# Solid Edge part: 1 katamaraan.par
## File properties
Author: Henri
Template: Normal.par
Last saved by: Henri
Revision: 92
Application: Solid Edge
Accuracy: 0,990
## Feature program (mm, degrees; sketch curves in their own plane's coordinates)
make body feature "unnamed MakeBodyFeature 1"
body pattern "unnamed BodyPattern 1"
pattern "unnamed Pattern 1"
sketch used by "ExtrudedCutout_22" plane through (0, 0, 0) normal (0, -1, 0) x-axis (1, 0, 0)
  arc centre (-269.3654, -198.9808) radius 198.9808 from (-425, -75) to (-269.3654, 0) cw
  line (-425, -75) -> (-425, 0)
  line (-425, 0) -> (-269.3654, 0)
extrude "ExtrudedCutout_22" cut finite 150 symmetric
fillet "Round_5" radius 10
thinwall "Thinwall_9"  Thickness = 5 mm
sketch for "unnamed Protrusion 1" plane through (0, 0, 0) normal (0, -1, 0) x-axis (1, 0, 0)
  line (-358, -40.9709) -> (-327, -40.9709)
  line (-327, -40.9709) -> (-327, -26.9709)
  line (-327, -26.9709) -> (-296, -26.9709)
  line (-296, -26.9709) -> (-296, -12.9709)
  line (-296, -12.9709) -> (-265, -12.9709)
  line (-265, -12.9709) -> (-265, 0)
  line (-265, 0) -> (-260, 0)
  line (-260, -142.3581) -> (-260, 0)
  line (-265, -142.3562) -> (-260, -142.3581)
  line (-265, -17.9709) -> (-265, -142.3562)
  line (-291, -17.9709) -> (-265, -17.9709)
  line (-291, -31.9709) -> (-291, -17.9709)
  line (-322, -31.9709) -> (-291, -31.9709)
  line (-322, -45.9709) -> (-322, -31.9709)
  line (-353, -45.9709) -> (-322, -45.9709)
  line (-353, -59.9709) -> (-353, -45.9709)
  line (-384, -59.9709) -> (-353, -59.9709)
  line (-384, -73.9709) -> (-384, -59.9709)
  line (-420, -73.9709) -> (-384, -73.9709)
  line (-420, -68.9709) -> (-420, -73.9709)
  line (-420, -68.9709) -> (-389, -68.9709)
  line (-389, -68.9709) -> (-389, -54.9709)
  line (-389, -54.9709) -> (-358, -54.9709)
  line (-358, -54.9709) -> (-358, -40.9709)
extrude "unnamed Protrusion 1" add through along -normal
sketch for "ExtrudedCutout_24" plane through (-260, 0, -71.179) normal (1, 0, 0) x-axis (0, 1, 0)
  line (22.5, -30.321) -> (22.5, 53.2082)
  line (22.5, 53.2082) -> (-22.5, 53.2082)
  line (-22.5, 53.2082) -> (-22.5, -30.321)
  line (-22.5, -30.321) -> (22.5, -30.321)
extrude "ExtrudedCutout_24" cut finite 5 along -normal
web network "WebNetwork_20"  Thickness = 3 mm
web network "WebNetwork_21"  Thickness = 5 mm
sketch used by "unnamed Cutout 1" plane through (2.5, 0, -49.25) normal (1, 0, 0) x-axis (0, 1, 0)
extrude "unnamed Cutout 1" cut through along -normal
sketch used by "unnamed Cutout 2" plane through (262.5, 0, -57.5536) normal (1, 0, 0) x-axis (0, 1, 0)
  line (-15, 52.5536) -> (15, 52.5536)
  line (-15, 52.5536) -> (-15, 17.5536)
  line (-15, 17.5536) -> (15, 17.5536)
  line (15, 17.5536) -> (15, 52.5536)
extrude "unnamed Cutout 2" cut through along -normal
sketch for "ExtrudedCutout_27" plane through (0, 0, -150) normal (0, 0, 1) x-axis (1, 0, 0)
  circle centre (-356.0086, 0) radius 2.5
extrude "ExtrudedCutout_27" cut finite 5 along +normal
body pattern "unnamed BodyPattern 2"
pattern "unnamed Pattern 2"
fillet "Round_26" radius 2.5
fillet "Round_27" radius 2.5
fillet "Round_28" radius 1.5
fillet "Round_29" radius 1.5
sketch for "unnamed Protrusion 2" plane through (0, -250, 0) normal (0, -1, 0) x-axis (1, 0, 0)
  line (-222.5, 0) -> (262.5, 0)
  line (262.5, 0) -> (262.5, -49)
  arc centre (261.5, -49) radius 1 from (261.5, -50) to (262.5, -49) ccw
  line (261.5, -50) -> (248.5, -50)
  arc centre (248.5, -49) radius 1 from (247.5, -49) to (248.5, -50) ccw
  line (247.5, -46) -> (247.5, -49)
  arc centre (246.5, -46) radius 1 from (246.5, -45) to (247.5, -46) cw
  line (158.5, -45) -> (246.5, -45)
  arc centre (158.5, -46) radius 1 from (157.5, -46) to (158.5, -45) cw
  line (157.5, -51.1299) -> (157.5, -46)
  arc centre (156.5, -51.1299) radius 1 from (156.5, -52.1299) to (157.5, -51.1299) ccw
  line (33.5, -52.1299) -> (156.5, -52.1299)
  arc centre (33.5, -51.1299) radius 1 from (32.5, -51.1299) to (33.5, -52.1299) ccw
  line (32.5, -46) -> (32.5, -51.1299)
  arc centre (31.5, -46) radius 1 from (31.5, -45) to (32.5, -46) cw
  line (-206.5, -45) -> (31.5, -45)
  arc centre (-206.5, -46) radius 1 from (-207.5, -46) to (-206.5, -45) cw
  line (-207.5, -46) -> (-207.5, -49)
  arc centre (-208.5, -49) radius 1 from (-208.5, -50) to (-207.5, -49) ccw
  line (-221.5, -50) -> (-208.5, -50)
  arc centre (-221.5, -49) radius 1 from (-222.5, -49) to (-221.5, -50) ccw
  line (-222.5, 0) -> (-222.5, -49)
extrude "unnamed Protrusion 2" add through along -normal
fillet "Round_30" radius 1.5
sketch for "ExtrudedCutout_47" plane through (0, 0, 0) normal (0, 0, 1) x-axis (1, 0, 0)
  line (202.5, -60) -> (212.5, -60)
  line (212.5, -60) -> (212.5, -55)
  line (212.5, -55) -> (202.5, -55)
  line (202.5, -55) -> (202.5, -60)
extrude "ExtrudedCutout_47" cut finite 5 along -normal
sketch for "ExtrudedCutout_49" plane through (0, 0, 0) normal (0, 0, 1) x-axis (1, 0, 0)
  line (-207.5, -75) -> (242.5, -75)
  line (242.5, -75) -> (242.5, -425)
  line (242.5, -425) -> (-207.5, -425)
  line (-207.5, -75) -> (-207.5, -425)
  line (-210, -72.5) -> (-210, -427.5)
  line (-210, -427.5) -> (245, -427.5)
  line (245, -427.5) -> (245, -72.5)
  line (245, -72.5) -> (-210, -72.5)
  dimension (linear) = 242.5
extrude "ExtrudedCutout_49" cut finite 37.5 along -normal
sketch for "unnamed Cutout 3" plane through (17.5, -72.5, -18.75) normal (0, -1, 0) x-axis (1, 0, 0)
  line (140, 18.75) -> (140, -18.75)
  line (80, -18.75) -> (140, -18.75)
  line (80, 18.75) -> (80, -18.75)
  line (140, 18.75) -> (80, 18.75)
extrude "unnamed Cutout 3" cut through along -normal
sketch for "unnamed Cutout 4" plane through (17.5, -427.5, -18.75) normal (0, 1, 0) x-axis (1, 0, 0)
extrude "unnamed Cutout 4" cut through along -normal
swept protrusion "unnamed SweptProtrusion 1"
swept protrusion "unnamed SweptProtrusion 2"
sketch for "unnamed Protrusion 3" #1 plane through (0, 0, 0) normal (0, -1, 0) x-axis (1, 0, 0)
  line (0, 0) -> (0, 0)
  line (98.5, -48.5) -> (156.5, -48.5)
  arc centre (156.5, -49.5) radius 1 from (156.5, -48.5) to (157.5, -49.5) cw
  line (157.5, -49.5) -> (157.5, -50)
  arc centre (156.5, -50) radius 1 from (156.5, -51) to (157.5, -50) ccw
  line (98.5, -51) -> (156.5, -51)
  arc centre (98.5, -50) radius 1 from (97.5, -50) to (98.5, -51) ccw
  line (97.5, -49.5) -> (97.5, -50)
  arc centre (98.5, -49.5) radius 1 from (97.5, -49.5) to (98.5, -48.5) cw
sketch for "unnamed Protrusion 3" #2 plane through (0, 0, 0) normal (0, -1, 0) x-axis (1, 0, 0)
  line (98.5, -61) -> (156.5, -61)
  arc centre (156.5, -62) radius 1 from (156.5, -61) to (157.5, -62) cw
  line (157.5, -62) -> (157.5, -62.5)
  arc centre (156.5, -62.5) radius 1 from (157.5, -62.5) to (156.5, -63.5) cw
  line (98.5, -63.5) -> (156.5, -63.5)
  arc centre (98.5, -62.5) radius 1 from (98.5, -63.5) to (97.5, -62.5) cw
  line (97.5, -62) -> (97.5, -62.5)
  arc centre (98.5, -62) radius 1 from (97.5, -62) to (98.5, -61) cw
sketch for "unnamed Protrusion 3" #3 plane through (0, 0, 0) normal (0, -1, 0) x-axis (1, 0, 0)
  line (98.5, -73.5) -> (156.5, -73.5)
  arc centre (156.5, -74.5) radius 1 from (156.5, -73.5) to (157.5, -74.5) cw
  line (157.5, -74.5) -> (157.5, -75)
  arc centre (156.5, -75) radius 1 from (157.5, -75) to (156.5, -76) cw
  line (98.5, -76) -> (156.5, -76)
  arc centre (98.5, -75) radius 1 from (97.5, -75) to (98.5, -76) ccw
  line (97.5, -74.5) -> (97.5, -75)
  arc centre (98.5, -74.5) radius 1 from (97.5, -74.5) to (98.5, -73.5) cw
sketch for "unnamed Protrusion 3" #4 plane through (0, 0, 0) normal (0, -1, 0) x-axis (1, 0, 0)
  line (98.5, -86) -> (156.5, -86)
  arc centre (156.5, -87) radius 1 from (156.5, -86) to (157.5, -87) cw
  line (157.5, -87) -> (157.5, -87.5)
  arc centre (156.5, -87.5) radius 1 from (157.5, -87.5) to (156.5, -88.5) cw
  line (98.5, -88.5) -> (156.5, -88.5)
  arc centre (98.5, -87.5) radius 1 from (97.5, -87.5) to (98.5, -88.5) ccw
  line (97.5, -87) -> (97.5, -87.5)
  arc centre (98.5, -87) radius 1 from (98.5, -86) to (97.5, -87) ccw
extrude "unnamed Protrusion 3" add through along +normal
sketch for "unnamed Cutout 5" plane through (152.5, 0, 0) normal (1, 0, 0) x-axis (0, 1, 0)
  line (0, -47.323) -> (-13.7556, -47.323)
  line (0, -89.2775) -> (-13.7556, -47.323)
  line (0, -47.323) -> (0, -89.2775)
extrude "unnamed Cutout 5" cut through along -normal
fillet "Round_32" radius 1
mirror "unnamed Mirror 1" of "unnamed SweptProtrusion 2", "unnamed SweptProtrusion 1" about plane through (0, -250, 0) normal (0, -1, 0)
swept protrusion "unnamed SweptProtrusion 3"
swept protrusion "unnamed SweptProtrusion 4"
mirror "unnamed Mirror 2" of "unnamed Protrusion 3", "unnamed Cutout 5" about plane through (0, -250, 0) normal (0, -1, 0)
extrude "unnamed Protrusion 4" add through
extrude "unnamed Cutout 6" cut through
sketch for "ExtrudedCutout_54" plane through (-81.4374, 2.895, -98.5) normal (0, 0, 1) x-axis (0, 1, 0)
  line (22.105, 191.0626) -> (-27.895, 191.0626)
  line (-27.895, 261.0626) -> (-27.895, 191.0626)
  line (22.105, 261.0626) -> (-27.895, 261.0626)
  line (22.105, 191.0626) -> (22.105, 261.0626)
extrude "ExtrudedCutout_54" cut finite 1 along -normal
mirror "unnamed Mirror 3" of "ExtrudedCutout_54" about plane through (0, -250, 0) normal (0, -1, 0)
extrude "unnamed Cutout 7" cut finite 1
sketch used by "ExtrudedProtrusion_60" plane through (73.8141, -228.1374, 0) normal (0, 0, 1) x-axis (0, 1, 0)
extrude "ExtrudedProtrusion_60" add finite 5 along +normal  FiniteDepth2 = 50 mm
sketch for "ExtrudedCutout_60" plane through (73.8141, -228.1374, 0) normal (0, 0, 1) x-axis (0, 1, 0)
  arc centre (-17.3626, -38.6859) radius 3 from (-17.3626, -41.6859) to (-14.3626, -38.6859) ccw
  line (-14.3626, -19.6859) -> (-14.3626, -38.6859)
  arc centre (-17.3626, -19.6859) radius 3 from (-17.3626, -16.6859) to (-14.3626, -19.6859) cw
  line (-26.3626, -16.6859) -> (-17.3626, -16.6859)
  arc centre (-26.3626, -19.6859) radius 3 from (-29.3626, -19.6859) to (-26.3626, -16.6859) cw
  line (-29.3626, -19.6859) -> (-29.3626, -38.6859)
  arc centre (-26.3626, -38.6859) radius 3 from (-26.3626, -41.6859) to (-29.3626, -38.6859) cw
  line (-26.3626, -41.6859) -> (-17.3626, -41.6859)
extrude "ExtrudedCutout_60" cut finite 5 along +normal  FiniteDepth2 = 45 mm
sketch for "unnamed Protrusion 5" #1 plane through (0, -25, 0) normal (0, -1, 0) x-axis (1, 0, 0)
sketch for "unnamed Protrusion 5" #2 plane through (0, -25, 0) normal (0, -1, 0) x-axis (1, 0, 0)
sketch for "unnamed Protrusion 5" #3 plane through (0, -25, 0) normal (0, -1, 0) x-axis (1, 0, 0)
  line (14.5, -11) -> (36, -11)
  arc centre (36, -12) radius 1 from (36, -11) to (37, -12) cw
  line (37, -12) -> (37, -20)
  arc centre (36, -20) radius 1 from (36, -21) to (37, -20) ccw
  line (14.5, -21) -> (36, -21)
  arc centre (14.5, -20) radius 1 from (13.5, -20) to (14.5, -21) ccw
  line (13.5, -20) -> (13.5, -12)
  arc centre (14.5, -12) radius 1 from (13.5, -12) to (14.5, -11) cw
sketch for "unnamed Protrusion 5" #4 plane through (0, -25, 0) normal (0, -1, 0) x-axis (1, 0, 0)
  arc centre (39, -12) radius 1 from (38, -12) to (39, -11) cw
  line (39, -11) -> (60.5, -11)
  arc centre (60.5, -12) radius 1 from (60.5, -11) to (61.5, -12) cw
  line (61.5, -12) -> (61.5, -20)
  arc centre (60.5, -20) radius 1 from (60.5, -21) to (61.5, -20) ccw
  line (39, -21) -> (60.5, -21)
  arc centre (39, -20) radius 1 from (39, -21) to (38, -20) cw
  line (38, -12) -> (38, -20)
sketch for "unnamed Protrusion 5" #5 plane through (0, -25, 0) normal (0, -1, 0) x-axis (1, 0, 0)
  line (14.5, -22) -> (36, -22)
  arc centre (36, -23) radius 1 from (36, -22) to (37, -23) cw
  line (37, -23) -> (37, -41)
  arc centre (36, -41) radius 1 from (36, -42) to (37, -41) ccw
  line (14.5, -42) -> (36, -42)
  arc centre (14.5, -41) radius 1 from (14.5, -42) to (13.5, -41) cw
  line (13.5, -41) -> (13.5, -23)
  arc centre (14.5, -23) radius 1 from (13.5, -23) to (14.5, -22) cw
sketch for "unnamed Protrusion 5" #6 plane through (0, -25, 0) normal (0, -1, 0) x-axis (1, 0, 0)
  line (39, -22) -> (60.5, -22)
  arc centre (60.5, -23) radius 1 from (60.5, -22) to (61.5, -23) cw
  line (61.5, -23) -> (61.5, -41)
  arc centre (60.5, -41) radius 1 from (60.5, -42) to (61.5, -41) ccw
  line (39, -42) -> (60.5, -42)
  arc centre (39, -41) radius 1 from (38, -41) to (39, -42) ccw
  line (38, -23) -> (38, -41)
  arc centre (39, -23) radius 1 from (38, -23) to (39, -22) cw
sketch for "unnamed Protrusion 5" #7 plane through (0, -25, 0) normal (0, -1, 0) x-axis (1, 0, 0)
  line (14.5, -43) -> (36, -43)
  arc centre (36, -44) radius 1 from (36, -43) to (37, -44) cw
  line (37, -44) -> (37, -57)
  arc centre (36, -57) radius 1 from (36, -58) to (37, -57) ccw
  line (14.5, -58) -> (36, -58)
  arc centre (14.5, -57) radius 1 from (14.5, -58) to (13.5, -57) cw
  line (13.5, -57) -> (13.5, -44)
  arc centre (14.5, -44) radius 1 from (13.5, -44) to (14.5, -43) cw
sketch for "unnamed Protrusion 5" #8 plane through (0, -25, 0) normal (0, -1, 0) x-axis (1, 0, 0)
  arc centre (39, -60) radius 1 from (38, -60) to (39, -59) cw
  line (39, -59) -> (60.5, -59)
  arc centre (60.5, -60) radius 1 from (61.5, -60) to (60.5, -59) ccw
  line (61.5, -60) -> (61.5, -68)
  arc centre (60.5, -68) radius 1 from (60.5, -69) to (61.5, -68) ccw
  line (60.5, -69) -> (39, -69)
  arc centre (39, -68) radius 1 from (38, -68) to (39, -69) ccw
  line (38, -60) -> (38, -68)
sketch for "unnamed Protrusion 5" #9 plane through (0, -25, 0) normal (0, -1, 0) x-axis (1, 0, 0)
extrude "unnamed Protrusion 5" add through along +normal
fillet "Round_34" radius 1
mirror "unnamed Mirror 4" of "unnamed Protrusion 5" about plane through (0, -250, 0) normal (0, -1, 0)
extrude "unnamed Protrusion 6" add through
sketch used by "unnamed Protrusion 7" plane through (0, -5, 0) normal (0, -1, 0) x-axis (1, 0, 0)
extrude "unnamed Protrusion 7" add through along -normal
swept protrusion "unnamed SweptProtrusion 5"
sketch for "ExtrudedProtrusion_65" plane through (-81.4299, 0, -98.5) normal (0, 0, 1) x-axis (0, 1, 0)
  circle centre (20, 48.5701) radius 1.25
extrude "ExtrudedProtrusion_65" add finite 62.5 along +normal
sketch for "unnamed Protrusion 8" #1 plane through (-180, 10, -81) normal (0, -1, 0) x-axis (1, 0, 0)
  circle centre (50.053, 37.5) radius 0.75
sketch for "unnamed Protrusion 8" #2 plane through (-180, 10, -81) normal (0, -1, 0) x-axis (1, 0, 0)
  circle centre (50, 22.5) radius 0.75
sketch for "unnamed Protrusion 8" #3 plane through (-180, 10, -81) normal (0, -1, 0) x-axis (1, 0, 0)
  circle centre (50, 7.5) radius 0.75
sketch for "unnamed Protrusion 8" #4 plane through (-180, 10, -81) normal (0, -1, 0) x-axis (1, 0, 0)
  circle centre (50, -7.5) radius 0.75
extrude "unnamed Protrusion 8" add through along -normal
fillet "Round_35" radius 1.5
mirror "unnamed Mirror 5" of "unnamed Protrusion 7" about plane through (0, -250, 0) normal (0, -1, 0)
extrude "unnamed Protrusion 9" add through
mirror "unnamed Mirror 6" of "unnamed SweptProtrusion 5", "ExtrudedProtrusion_65", "unnamed Protrusion 8" about plane through (0, -250, 0) normal (0, -1, 0)
swept protrusion "unnamed SweptProtrusion 6"
extrude "unnamed Protrusion 10" add finite 62.5
extrude "unnamed Protrusion 11" add through
fillet "Round_36" radius 1.5
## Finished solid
Body 1: solid body, 756 faces, 1844 edges, 1096 vertices, 2 internal voids.
  Faces by surface: plane 274, cylinder 228, blend 120, sphere 60, offset 40, spline 34
  Edges by curve: intersection 794, line 702, circle 342, curve on surface 6
Body 2: solid body, 4 faces, 7 edges, 5 vertices.
  Faces by surface: plane 3, spline 1
  Edges by curve: line 3, curve on surface 2, circle 1, spline 1
Bounding box of the edges (mm; curved faces can reach further): 850.000 x 646.544 x 155.000, from (-425, -573.4364, -150) to (425, 73.1078, 5).
Cylindrical faces by radius (mm): R0.75 x8, R1 x146, R1.25 x4, R1.5 x36, R2.5 x24, R3 x4, R10 x4, R198.9808 x2
Spherical faces by radius (mm): R1 x32, R1.5 x16, R2.5 x12
Planar faces by outward normal: +x 59, +y 16, +z 52, -x 64, -y 17, -z 57, oblique 12
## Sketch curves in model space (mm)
circle centre (-130, 10, -88.5) radius 0.75
circle centre (-130, 10, -73.5) radius 0.75
circle centre (-129.947, 10, -43.5) radius 0.75
circle centre (-130, 10, -58.5) radius 0.75
line (-138.1822, 10, -43.5) -> (-121.7119, 10, -43.5)
line (-139.7989, 10, -58.5) -> (-123.7328, 10, -58.5)
line (-141.5166, 10, -73.5) -> (-119.8931, 10, -73.5)
line (-141.5166, 10, -88.5) -> (-117.8722, 10, -88.5)
line (-130, 10, -20.6012) -> (-130, 10, -101.0326)
circle centre (-130, 20, -98.5) radius 1.25
line (-130, -8.4576, -98.5) -> (-130, 25.6531, -98.5)
line (-134.8834, 20, -98.5) -> (-121.6792, 20, -98.5)
circle centre (-230, 0, -33.5) radius 1.25
arc centre (61.5, -25, -11) radius 1 from (61.5, -25, -10) through (62.2274, -25, -10.3138) to (62.5, -25, -11)
line (62.5, -25, -11) -> (62.5, -25, -69)
arc centre (61.5, -25, -69) radius 1 from (61.5, -25, -70) through (62.2274, -25, -69.6862) to (62.5, -25, -69)
line (61.5, -25, -70) -> (13.5, -25, -70)
arc centre (13.5, -25, -69) radius 1 from (12.5, -25, -69) through (12.8138, -25, -69.7274) to (13.5, -25, -70)
line (12.5, -25, -69) -> (12.5, -25, -11)
arc centre (13.5, -25, -11) radius 1 from (12.5, -25, -11) through (12.8138, -25, -10.2726) to (13.5, -25, -10)
line (13.5, -25, -10) -> (61.5, -25, -10)
arc centre (14.5, -25, -23) radius 1 from (13.5, -25, -23) through (13.8138, -25, -22.2726) to (14.5, -25, -22)
line (14.5, -25, -22) -> (36, -25, -22)
arc centre (36, -25, -23) radius 1 from (36, -25, -22) through (36.7274, -25, -22.3138) to (37, -25, -23)
line (37, -25, -23) -> (37, -25, -41)
arc centre (36, -25, -41) radius 1 from (36, -25, -42) through (36.7274, -25, -41.6862) to (37, -25, -41)
line (14.5, -25, -42) -> (36, -25, -42)
arc centre (14.5, -25, -41) radius 1 from (14.5, -25, -42) through (13.7726, -25, -41.6862) to (13.5, -25, -41)
line (13.5, -25, -41) -> (13.5, -25, -23)
arc centre (36, -25, -12) radius 1 from (36, -25, -11) through (36.7274, -25, -11.3138) to (37, -25, -12)
line (37, -25, -12) -> (37, -25, -20)
arc centre (36, -25, -20) radius 1 from (36, -25, -21) through (36.7274, -25, -20.6862) to (37, -25, -20)
line (14.5, -25, -21) -> (36, -25, -21)
arc centre (14.5, -25, -20) radius 1 from (13.5, -25, -20) through (13.8138, -25, -20.7274) to (14.5, -25, -21)
line (13.5, -25, -20) -> (13.5, -25, -12)
arc centre (14.5, -25, -12) radius 1 from (13.5, -25, -12) through (13.8138, -25, -11.2726) to (14.5, -25, -11)
line (14.5, -25, -11) -> (36, -25, -11)
arc centre (60.5, -25, -41) radius 1 from (60.5, -25, -42) through (61.2274, -25, -41.6862) to (61.5, -25, -41)
line (39, -25, -42) -> (60.5, -25, -42)
arc centre (39, -25, -41) radius 1 from (38, -25, -41) through (38.3138, -25, -41.7274) to (39, -25, -42)
line (38, -25, -23) -> (38, -25, -41)
arc centre (39, -25, -23) radius 1 from (38, -25, -23) through (38.3138, -25, -22.2726) to (39, -25, -22)
line (39, -25, -22) -> (60.5, -25, -22)
arc centre (60.5, -25, -23) radius 1 from (60.5, -25, -22) through (61.2274, -25, -22.3138) to (61.5, -25, -23)
line (61.5, -25, -23) -> (61.5, -25, -41)
arc centre (14.5, -25, -68) radius 1 from (13.5, -25, -68) through (13.8138, -25, -68.7274) to (14.5, -25, -69)
line (13.5, -25, -68) -> (13.5, -25, -60)
arc centre (14.5, -25, -60) radius 1 from (13.5, -25, -60) through (13.8138, -25, -59.2726) to (14.5, -25, -59)
line (14.5, -25, -59) -> (36, -25, -59)
arc centre (36, -25, -60) radius 1 from (36, -25, -59) through (36.7274, -25, -59.3138) to (37, -25, -60)
line (37, -25, -60) -> (37, -25, -68)
arc centre (36, -25, -68) radius 1 from (36, -25, -69) through (36.7274, -25, -68.6862) to (37, -25, -68)
line (36, -25, -69) -> (14.5, -25, -69)
arc centre (60.5, -25, -20) radius 1 from (60.5, -25, -21) through (61.2274, -25, -20.6862) to (61.5, -25, -20)
line (61.5, -25, -12) -> (61.5, -25, -20)
arc centre (60.5, -25, -12) radius 1 from (60.5, -25, -11) through (61.2274, -25, -11.3138) to (61.5, -25, -12)
line (39, -25, -11) -> (60.5, -25, -11)
arc centre (39, -25, -12) radius 1 from (38, -25, -12) through (38.3138, -25, -11.2726) to (39, -25, -11)
line (38, -25, -12) -> (38, -25, -20)
arc centre (39, -25, -20) radius 1 from (39, -25, -21) through (38.2726, -25, -20.6862) to (38, -25, -20)
line (39, -25, -21) -> (60.5, -25, -21)
arc centre (60.5, -25, -44) radius 1 from (60.5, -25, -43) through (61.2274, -25, -43.3138) to (61.5, -25, -44)
line (61.5, -25, -44) -> (61.5, -25, -57)
arc centre (60.5, -25, -57) radius 1 from (60.5, -25, -58) through (61.2274, -25, -57.6862) to (61.5, -25, -57)
line (39, -25, -58) -> (60.5, -25, -58)
arc centre (39, -25, -57) radius 1 from (39, -25, -58) through (38.2726, -25, -57.6862) to (38, -25, -57)
line (38, -25, -44) -> (38, -25, -57)
arc centre (39, -25, -44) radius 1 from (38, -25, -44) through (38.3138, -25, -43.2726) to (39, -25, -43)
line (39, -25, -43) -> (60.5, -25, -43)
arc centre (60.5, -25, -60) radius 1 from (61.5, -25, -60) through (61.1862, -25, -59.2726) to (60.5, -25, -59)
line (61.5, -25, -60) -> (61.5, -25, -68)
arc centre (60.5, -25, -68) radius 1 from (60.5, -25, -69) through (61.2274, -25, -68.6862) to (61.5, -25, -68)
line (60.5, -25, -69) -> (39, -25, -69)
arc centre (39, -25, -68) radius 1 from (38, -25, -68) through (38.3138, -25, -68.7274) to (39, -25, -69)
line (38, -25, -60) -> (38, -25, -68)
arc centre (39, -25, -60) radius 1 from (38, -25, -60) through (38.3138, -25, -59.2726) to (39, -25, -59)
line (39, -25, -59) -> (60.5, -25, -59)
arc centre (14.5, -25, -44) radius 1 from (13.5, -25, -44) through (13.8138, -25, -43.2726) to (14.5, -25, -43)
line (14.5, -25, -43) -> (36, -25, -43)
arc centre (36, -25, -44) radius 1 from (36, -25, -43) through (36.7274, -25, -43.3138) to (37, -25, -44)
line (37, -25, -44) -> (37, -25, -57)
arc centre (36, -25, -57) radius 1 from (36, -25, -58) through (36.7274, -25, -57.6862) to (37, -25, -57)
line (14.5, -25, -58) -> (36, -25, -58)
arc centre (14.5, -25, -57) radius 1 from (14.5, -25, -58) through (13.7726, -25, -57.6862) to (13.5, -25, -57)
line (13.5, -25, -57) -> (13.5, -25, -44)
line (-342.5, -25, -98.5) -> (-272.5, -25, -98.5)
line (-342.5, 25, -98.5) -> (-342.5, -25, -98.5)
line (-272.5, 25, -98.5) -> (-342.5, 25, -98.5)
line (-272.5, 25, -98.5) -> (-272.5, -25, -98.5)
line (83.5, -254.5, 0) -> (83.5, -245.5, 0)
arc centre (93.5, -245.5, 0) radius 10 from (83.5, -245.5, 0) through (86.6376, -238.2263, 0) to (93.5, -235.5, 0)
line (93.5, -235.5, 0) -> (112.5, -235.5, 0)
arc centre (112.5, -245.5, 0) radius 10 from (122.5, -245.5, 0) through (119.3624, -238.2263, 0) to (112.5, -235.5, 0)
line (122.5, -254.5, 0) -> (122.5, -245.5, 0)
arc centre (112.5, -254.5, 0) radius 10 from (122.5, -254.5, 0) through (119.3624, -261.7737, 0) to (112.5, -264.5, 0)
line (93.5, -264.5, 0) -> (112.5, -264.5, 0)
arc centre (93.5, -254.5, 0) radius 10 from (93.5, -264.5, 0) through (86.2263, -261.3624, 0) to (83.5, -254.5, 0)
line (152.5, 0, -47.323) -> (152.5, -13.7556, -47.323)
line (152.5, 0, -47.323) -> (152.5, 0, -89.2775)
line (152.5, 0, -89.2775) -> (152.5, -13.7556, -47.323)
line (87.2351, 0, -98.5) -> (168.5414, 0, -98.5)
arc centre (98.5, 0, -50) radius 1 from (97.5, 0, -50) through (97.8138, 0, -50.7274) to (98.5, 0, -51)
line (98.5, 0, -51) -> (156.5, 0, -51)
arc centre (156.5, 0, -50) radius 1 from (156.5, 0, -51) through (157.2274, 0, -50.6862) to (157.5, 0, -50)
line (157.5, 0, -49.5) -> (157.5, 0, -50)
arc centre (156.5, 0, -49.5) radius 1 from (156.5, 0, -48.5) through (157.2274, 0, -48.8138) to (157.5, 0, -49.5)
line (98.5, 0, -48.5) -> (156.5, 0, -48.5)
arc centre (98.5, 0, -49.5) radius 1 from (97.5, 0, -49.5) through (97.8138, 0, -48.7726) to (98.5, 0, -48.5)
line (97.5, 0, -49.5) -> (97.5, 0, -50)
arc centre (156.5, 0, -87.5) radius 1 from (157.5, 0, -87.5) through (157.1862, 0, -88.2274) to (156.5, 0, -88.5)
line (98.5, 0, -88.5) -> (156.5, 0, -88.5)
arc centre (98.5, 0, -87.5) radius 1 from (97.5, 0, -87.5) through (97.8138, 0, -88.2274) to (98.5, 0, -88.5)
line (97.5, 0, -87) -> (97.5, 0, -87.5)
arc centre (98.5, 0, -87) radius 1 from (98.5, 0, -86) through (97.7726, 0, -86.3138) to (97.5, 0, -87)
line (98.5, 0, -86) -> (156.5, 0, -86)
arc centre (156.5, 0, -87) radius 1 from (156.5, 0, -86) through (157.2274, 0, -86.3138) to (157.5, 0, -87)
line (157.5, 0, -87) -> (157.5, 0, -87.5)
arc centre (156.5, 0, -75) radius 1 from (157.5, 0, -75) through (157.1862, 0, -75.7274) to (156.5, 0, -76)
line (157.5, 0, -74.5) -> (157.5, 0, -75)
arc centre (156.5, 0, -74.5) radius 1 from (156.5, 0, -73.5) through (157.2274, 0, -73.8138) to (157.5, 0, -74.5)
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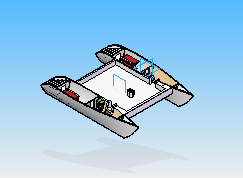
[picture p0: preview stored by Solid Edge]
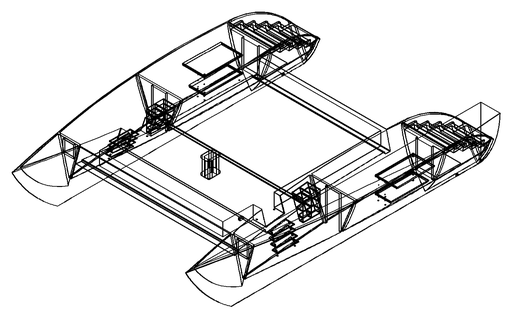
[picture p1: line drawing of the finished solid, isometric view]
